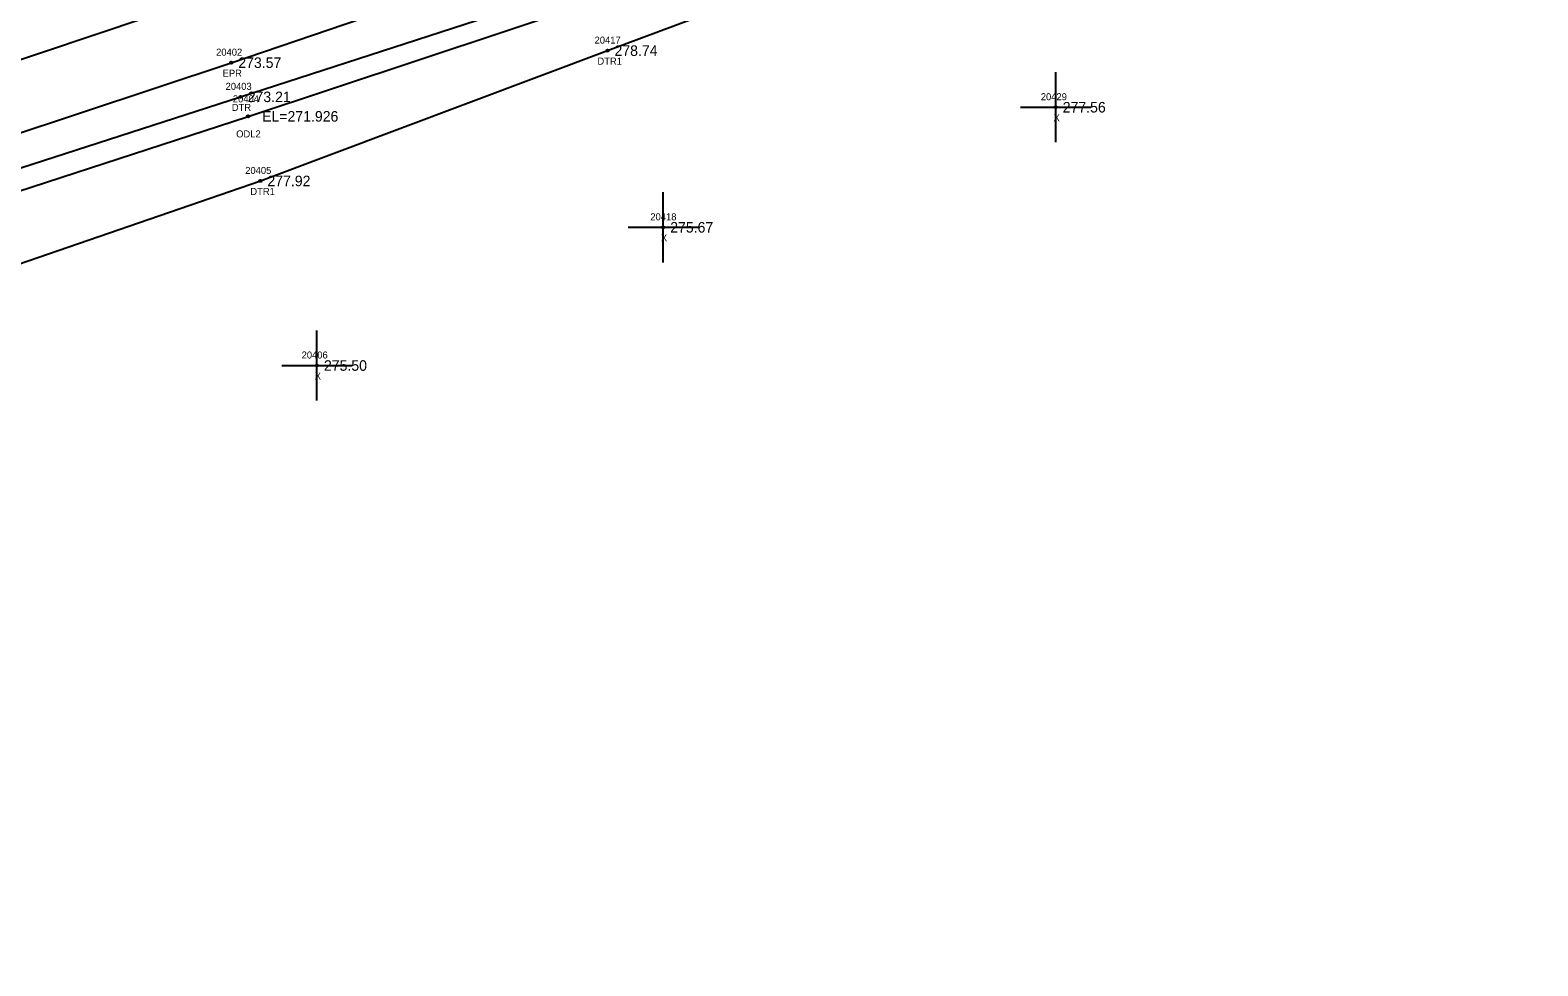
# Model space of a CAD drawing. Extents: x 2275563 to 2277161, y 1075719 to 1076412.
# Drawn here: x 2276928.6 to 2277143.5, y 1076060.8 to 1076194.1 of the extents above; entities that cross this region are included whole.
import ezdxf

# ---------------------------------------------------------------- set-up
doc = ezdxf.new("R2010")
doc.units = 0
for name, color, linetype in [('RD_DTM_BkLn1', 7, 'Continuous'), ('RD_EX_H2O', 7, 'Continuous'), ('RD_EX_H2O_txCode', 7, 'Continuous'), ('RD_EX_Misc', 7, 'Continuous'), ('RD_EX_Misc_txCode', 7, 'Continuous'), ('RD_EX_Road', 7, 'Continuous'), ('RD_EX_Road_txCode', 7, 'Continuous'), ('RD_EX_TX_H2O_ELEV', 7, 'Continuous'), ('RD_EX_TX_Misc_ELEV', 7, 'Continuous'), ('RD_EX_TX_Road_ELEV', 7, 'Continuous'), ('RD_SMD_Locator', 7, 'Continuous')]:
    doc.layers.add(name, color=color, linetype=linetype)

msp = doc.modelspace()

# ---------------------------------------------------------------- linework, layer by layer
at = {"layer": 'RD_DTM_BkLn1'}
msp.add_lwpolyline([(2276380.47, 1076073.8), (2276432.36, 1076079.4), (2276487.41, 1076086.42), (2276535.62, 1076093.32), (2276578.15, 1076099.97), (2276622.03, 1076107.93), (2276668.51, 1076117.27), (2276714.2, 1076127.81), (2276762.94, 1076140.11), (2276806.88, 1076151.96), (2276854.94, 1076166.29), (2276899.73, 1076180.7), (2276952.88, 1076198.57), (2277000.46, 1076214.72), (2277057.1, 1076234.01), (2277134.93, 1076261.07)], dxfattribs=at)
at = {"layer": 'RD_EX_H2O'}
for points in [[(2276577.32, 1076064.99), (2276581.11, 1076068.71), (2276607.06, 1076074.47), (2276628.35, 1076084.13), (2276659.02, 1076095.85), (2276671.39, 1076099.39), (2276718.28, 1076111.88), (2276766.76, 1076124.15), (2276811.4, 1076137.27), (2276858.53, 1076152.16), (2276905.48, 1076167.47), (2276958.61, 1076184.59), (2277007.29, 1076200.4), (2277063.09, 1076219.53), (2277141.85, 1076245.35)], [(2276577.32, 1076064.99), (2276608.07, 1076069.56), (2276629.89, 1076080.39), (2276660.01, 1076094.12), (2276672.11, 1076097.43), (2276718.92, 1076109.66), (2276767.33, 1076122.4), (2276812.13, 1076135.39), (2276859.85, 1076149.89), (2276906.21, 1076164.41), (2276959.66, 1076181.81), (2277008.45, 1076198), (2277064.73, 1076216.97), (2277142.57, 1076243.16)], [(2276577.32, 1076064.99), (2276585.61, 1076060.77), (2276608.72, 1076065.79), (2276630.67, 1076076.21), (2276642.12, 1076079.44), (2276661.39, 1076087.16), (2276674.74, 1076089.6), (2276720.85, 1076101.92), (2276769.56, 1076115.83), (2276815.16, 1076127.06), (2276862.66, 1076139.65), (2276909.53, 1076154.75), (2276961.42, 1076172.61), (2277010.89, 1076191.18), (2277066.25, 1076211.87), (2277143.49, 1076241.1)]]:
    msp.add_lwpolyline(points, dxfattribs=at)
at = {"layer": 'RD_EX_Misc'}
for p, q in [((2277074.77, 1076178.11), (2277074.77, 1076188.11)), ((2277069.77, 1076183.11), (2277079.77, 1076183.11)), ((2277018.83, 1076161), (2277018.83, 1076171)), ((2277013.83, 1076166), (2277023.83, 1076166)), ((2276969.48, 1076141.31), (2276969.48, 1076151.31)), ((2276964.48, 1076146.31), (2276974.48, 1076146.31))]:
    msp.add_line(p, q, dxfattribs=at)
at = {"layer": 'RD_EX_Road'}
msp.add_lwpolyline([(2276381.27, 1076063.04), (2276433.15, 1076069.16), (2276488.59, 1076076.23), (2276537.45, 1076083.34), (2276579.64, 1076090.09), (2276624.07, 1076098.24), (2276670.54, 1076107.46), (2276716.67, 1076118.09), (2276765.18, 1076130.28), (2276809.58, 1076142.25), (2276856.93, 1076156.58), (2276903.53, 1076171.63), (2276957.27, 1076189.46), (2277005.85, 1076206.01), (2277060.98, 1076225.07), (2277139.5, 1076252.36)], dxfattribs=at)
at = {"layer": 'RD_SMD_Locator'}
for centre in [(2277010.89, 1076191.18), (2276957.27, 1076189.46), (2276958.61, 1076184.59), (2277074.77, 1076183.11), (2276959.66, 1076181.81), (2276961.42, 1076172.61), (2277018.83, 1076166), (2276969.48, 1076146.31)]:
    msp.add_circle(centre, 0.15, dxfattribs=at)

# ---------------------------------------------------------------- texts
at = {"layer": 'RD_EX_H2O_txCode'}
for s, p in [('20417', (2277009.05, 1076192.18)), ('DTR1', (2277009.46, 1076189.18)), ('20403', (2276956.46, 1076185.59)), ('20404', (2276957.5, 1076183.81)), ('DTR', (2276957.35, 1076182.59)), ('ODL2', (2276957.97, 1076178.81)), ('20405', (2276959.26, 1076173.61)), ('DTR1', (2276959.99, 1076170.61))]:
    msp.add_text(s, height=1, dxfattribs=at).set_placement(p)
at = {"layer": 'RD_EX_Misc_txCode'}
for s, p in [('20429', (2277072.65, 1076184.11)), ('X', (2277074.46, 1076181.11)), ('20418', (2277017, 1076167)), ('X', (2277018.51, 1076164)), ('20406', (2276967.3, 1076147.31)), ('X', (2276969.17, 1076144.31))]:
    msp.add_text(s, height=1, dxfattribs=at).set_placement(p)
at = {"layer": 'RD_EX_Road_txCode'}
for s, p in [('20402', (2276955.11, 1076190.46)), ('EPR', (2276956.04, 1076187.46))]:
    msp.add_text(s, height=1, dxfattribs=at).set_placement(p)
at = {"layer": 'RD_EX_TX_H2O_ELEV'}
for s, p in [('278.74', (2277011.89, 1076190.43)), ('273.21', (2276959.61, 1076183.84)), ('EL=271.926', (2276961.66, 1076181.06)), ('277.92', (2276962.42, 1076171.86))]:
    msp.add_text(s, height=1.5, dxfattribs=at).set_placement(p)
at = {"layer": 'RD_EX_TX_Misc_ELEV'}
for s, p in [('277.56', (2277075.77, 1076182.36)), ('275.67', (2277019.83, 1076165.25)), ('275.50', (2276970.48, 1076145.56))]:
    msp.add_text(s, height=1.5, dxfattribs=at).set_placement(p)
at = {"layer": 'RD_EX_TX_Road_ELEV'}
msp.add_text('273.57', height=1.5, dxfattribs=at).set_placement((2276958.27, 1076188.71))

doc.saveas('drawing.dxf')
